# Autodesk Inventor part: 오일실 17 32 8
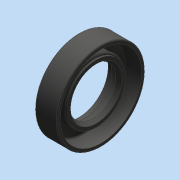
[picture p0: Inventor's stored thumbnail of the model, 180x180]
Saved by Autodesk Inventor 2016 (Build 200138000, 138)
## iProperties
Created: 2024-09
Part Number: 오일실 17 32 8
Material: 일반
Description: 오일-실
Document SubType Name: Modeling
Designer: pc-7
Density: 1 g/cm^3
Appearance: 기본값
Author: jhkim
Sending System: Autodesk Inventor 2025
Preprocessor: ST-DEVELOPER v20
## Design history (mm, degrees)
node "오일실 17 32 81"
node "솔리드1"
body "Solid1"
